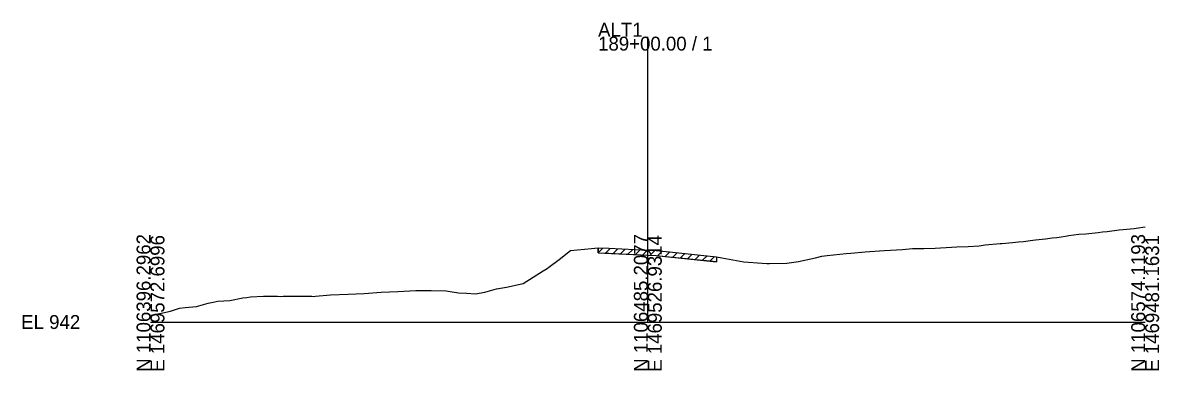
# Model space of a CAD drawing. Extents: x -26 to 2203, y -10 to 19568.
# Drawn here: x 1974.3 to 2202.8, y 10990.3 to 11060.2 of the extents above; entities that cross this region are included whole.
import ezdxf

# ---------------------------------------------------------------- set-up
doc = ezdxf.new("R2010")
doc.units = 0
for name, color, linetype in [('RD_GPK_XS_Cell', 7, 'Continuous'), ('RD_XS_ExGround', 7, 'Continuous'), ('RD_XS_ExPaveRet', 7, 'Continuous')]:
    doc.layers.add(name, color=color, linetype=linetype)

msp = doc.modelspace()

# ---------------------------------------------------------------- linework, layer by layer
at = {"layer": 'RD_GPK_XS_Cell'}
for p, q in [((2100, 11000), (2100, 11057.36)), ((2000, 11000), (2100, 11000)), ((2100, 11000), (2200, 11000))]:
    msp.add_line(p, q, dxfattribs=at)
at = {"layer": 'RD_XS_ExGround'}
msp.add_lwpolyline([(2000, 11001.35), (2000.44, 11001.45), (2002.48, 11001.87), (2004.01, 11002.16), (2005.85, 11002.76), (2006.99, 11002.92), (2009.23, 11003.14), (2011.6, 11003.8), (2012.6, 11004), (2012.92, 11004.09), (2013.55, 11004.17), (2015.98, 11004.33), (2018.55, 11004.84), (2019.35, 11004.92), (2020.1, 11005.07), (2022.72, 11005.17), (2025.51, 11005.17), (2026.1, 11005.16), (2026.66, 11005.18), (2029.47, 11005.21), (2032.46, 11005.19), (2032.85, 11005.16), (2033.21, 11005.2), (2036.22, 11005.47), (2039.76, 11005.62), (2042.97, 11005.74), (2046.37, 11006.01), (2049.72, 11006.14), (2053.32, 11006.35), (2056.46, 11006.32), (2059.43, 11006.24), (2059.84, 11006.21), (2061.93, 11005.87), (2063.55, 11005.79), (2065.38, 11005.64), (2067.21, 11006.02), (2068.15, 11006.27), (2069.58, 11006.65), (2071.6, 11007.04), (2074.92, 11007.73), (2078.98, 11010.32), (2079.75, 11010.78), (2080.08, 11011.02), (2082.18, 11012.56), (2084.47, 11014.4), (2088.69, 11014.8), (2090, 11014.93), (2092.18, 11014.82), (2100, 11014.45), (2101.7, 11014.36), (2103.72, 11014.16), (2113.81, 11013.13), (2114.88, 11012.93), (2119.29, 11012.12), (2122.99, 11011.85), (2123.95, 11011.78), (2124.44, 11011.76), (2127.92, 11011.81), (2130.31, 11012.2), (2133.7, 11012.9), (2134.96, 11013.22), (2136.09, 11013.36), (2139.89, 11013.79), (2140.82, 11013.84), (2143.72, 11014.1), (2144.64, 11014.17), (2146.57, 11014.29), (2147.57, 11014.4), (2151.2, 11014.61), (2153.25, 11014.78), (2154.31, 11014.76), (2155.48, 11014.75), (2157.75, 11014.83), (2161.07, 11015.05), (2162.16, 11015.11), (2164.44, 11015.16), (2166.62, 11015.35), (2167.81, 11015.49), (2170.86, 11015.79), (2171.19, 11015.82), (2173.3, 11016.02), (2174.56, 11016.12), (2175.53, 11016.22), (2177.41, 11016.45), (2177.93, 11016.51), (2179.98, 11016.73), (2181.31, 11016.9), (2182.21, 11017), (2183.97, 11017.26), (2184.68, 11017.37), (2186.67, 11017.63), (2188.06, 11017.74), (2190.52, 11018.02), (2191.43, 11018.11), (2192.39, 11018.23), (2194.8, 11018.52), (2195.58, 11018.59), (2197.08, 11018.75), (2197.8, 11018.83), (2198.18, 11018.88), (2200, 11019.12)], dxfattribs=at)
at = {"layer": 'RD_XS_ExPaveRet'}
for p, q in [((2090, 11014.93), (2090, 11013.93)), ((2090, 11013.94), (2090, 11014.92)), ((2090, 11013.94), (2090.94, 11014.87)), ((2090, 11013.94), (2092.7, 11013.81)), ((2090, 11013.93), (2092.18, 11013.82)), ((2090, 11013.92), (2090.01, 11013.92)), ((2090.01, 11013.92), (2091.96, 11013.82)), ((2091.5, 11013.87), (2092.44, 11014.8)), ((2091.96, 11013.82), (2100, 11013.44)), ((2092.18, 11013.82), (2100, 11013.45)), ((2092.7, 11013.81), (2100, 11013.46)), ((2093, 11013.77), (2093.96, 11014.73)), ((2094.5, 11013.7), (2095.46, 11014.66)), ((2096, 11013.63), (2096.96, 11014.59)), ((2097.5, 11013.56), (2098.46, 11014.51)), ((2099, 11013.49), (2099.96, 11014.44)), ((2100, 11013.46), (2101.69, 11013.38)), ((2100.5, 11013.44), (2101.44, 11014.37)), ((2101.69, 11013.38), (2104.27, 11013.12)), ((2101.7, 11013.36), (2103.72, 11013.16)), ((2101.7, 11013.36), (2103.48, 11013.18)), ((2102, 11013.35), (2102.89, 11014.24)), ((2103.48, 11013.18), (2113.81, 11012.12)), ((2103.5, 11013.17), (2104.41, 11014.08)), ((2103.72, 11013.16), (2113.81, 11012.13)), ((2104.27, 11013.12), (2113.81, 11012.14)), ((2105, 11013.02), (2105.91, 11013.93)), ((2106.5, 11012.87), (2107.41, 11013.77)), ((2108, 11012.71), (2108.91, 11013.62)), ((2109.5, 11012.56), (2110.41, 11013.47)), ((2111, 11012.41), (2111.91, 11013.31)), ((2112.5, 11012.25), (2113.41, 11013.16)), ((2113.81, 11013.14), (2113.81, 11012.14)), ((2113.81, 11013.13), (2113.81, 11012.13)), ((2113.81, 11012.14), (2113.81, 11012.14))]:
    msp.add_line(p, q, dxfattribs=at)

# ---------------------------------------------------------------- texts
at = {"layer": 'RD_GPK_XS_Cell'}
for s, p in [('ALT1', (2090, 11057.36)), ('189+00.00 / 1', (2090, 11054.56)), ('EL 942', (1974, 10998.6))]:
    msp.add_text(s, height=2.8, dxfattribs=at).set_placement(p)
for s, p in [('N 1106396.2962', (2000, 10990)), ('E 1469572.6996', (2002.8, 10990)), ('N 1106485.2077', (2100, 10990)), ('E 1469526.9314', (2102.8, 10990)), ('N 1106574.1193', (2200, 10990)), ('E 1469481.1631', (2202.8, 10990))]:
    msp.add_text(s, height=2.8, rotation=90, dxfattribs=at).set_placement(p)

doc.saveas('drawing.dxf')
